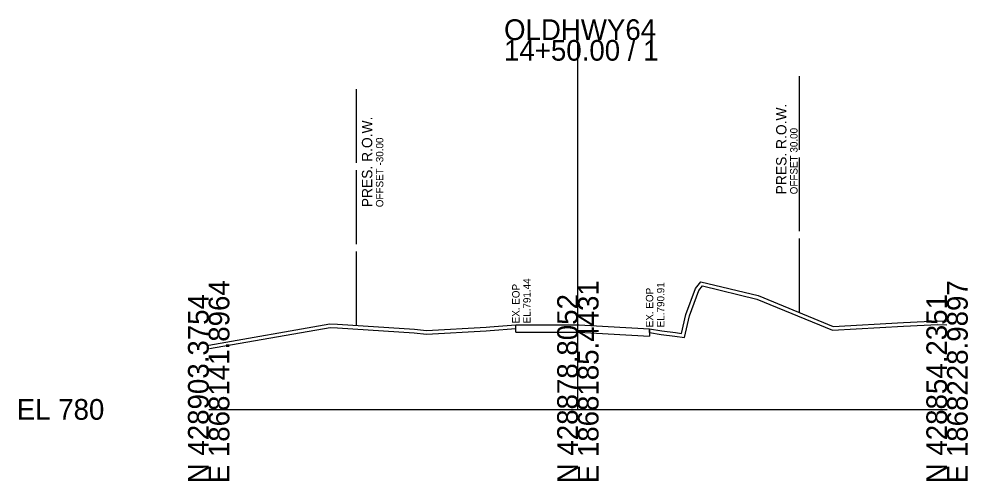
# Model space of a CAD drawing. Extents: x -452 to 3103, y -29 to 1600.
# Drawn here: x -25.7 to 102.8, y -17.7 to 44.8 of the extents above; entities that cross this region are included whole.
import ezdxf

# ---------------------------------------------------------------- set-up
doc = ezdxf.new("R2010")
doc.units = 0
for name, color, linetype in [('DESIGN - SHEET - Light Grid', 7, 'Continuous'), ('SURVEY - GROUND - Bottom of Topsoil Layer', 7, 'Continuous'), ('SURVEY - GROUND - Existing Pavement Layer', 7, 'Continuous'), ('SURVEY - GROUND - Existing Pavement Text', 7, 'Continuous'), ('SURVEY - GROUND - Top of Ground', 7, 'Continuous'), ('SURVEY - PROPERTY - ROW Lines', 7, 'Continuous'), ('SURVEY - PROPERTY - ROW Lines Text', 7, 'Continuous')]:
    doc.layers.add(name, color=color, linetype=linetype)

msp = doc.modelspace()

# ---------------------------------------------------------------- linework, layer by layer
at = {"layer": 'DESIGN - SHEET - Light Grid'}
for p, q in [((50, -8), (50, 42)), ((0, -8), (50, -8)), ((50, -8), (100, -8))]:
    msp.add_line(p, q, dxfattribs=at)
at = {"layer": 'SURVEY - GROUND - Bottom of Topsoil Layer'}
for p, q in [((41.6, 2.93), (41.6, 3.44)), ((59.71, 2.41), (59.71, 2.91))]:
    msp.add_line(p, q, dxfattribs=at)
for points in [[(59.71, 2.41), (61.3, 2.14), (63.14, 1.91), (64.43, 1.72), (65.12, 4.68), (66.4, 8.11), (66.87, 8.71), (74.26, 6.94), (84.49, 2.71), (94.11, 3.28), (98.74, 3.47), (99.98, 3.43)], [(0.09, 0.22), (16.45, 3.07), (17.43, 3.02), (27.85, 2.37), (29.5, 2.16), (37.6, 2.63), (38.12, 2.69), (41.6, 2.93)]]:
    msp.add_lwpolyline(points, dxfattribs=at)
at = {"layer": 'SURVEY - GROUND - Existing Pavement Layer'}
for p, q in [((41.6, 2.44), (41.6, 3.44)), ((59.71, 2.91), (59.71, 1.91)), ((41.6, 2.44), (45.14, 2.46)), ((45.14, 2.46), (49.07, 2.44)), ((49.07, 2.44), (50.18, 2.44)), ((50.18, 2.44), (54.09, 2.23)), ((54.09, 2.23), (59.71, 1.91))]:
    msp.add_line(p, q, dxfattribs=at)
at = {"layer": 'SURVEY - GROUND - Top of Ground'}
msp.add_lwpolyline([(0, 0.71), (16.42, 3.57), (17.46, 3.52), (27.89, 2.87), (29.51, 2.66), (37.56, 3.13), (38.07, 3.19), (41.6, 3.44), (45.14, 3.46), (49.07, 3.44), (50.18, 3.44), (54.09, 3.23), (59.71, 2.91), (61.37, 2.63), (63.2, 2.4), (64.05, 2.28), (64.64, 4.83), (65.95, 8.36), (66.67, 9.27), (74.42, 7.42), (84.57, 3.21), (94.08, 3.78), (98.74, 3.97), (100, 3.93)], dxfattribs=at)
at = {"layer": 'SURVEY - PROPERTY - ROW Lines'}
for p, q in [((80, 27.11), (80, 37.11)), ((20, 25.36), (20, 35.36)), ((80, 16.11), (80, 26.11)), ((20, 14.36), (20, 24.36)), ((80, 5.11), (80, 15.11)), ((20, 3.36), (20, 13.36))]:
    msp.add_line(p, q, dxfattribs=at)

# ---------------------------------------------------------------- texts
at = {"layer": 'DESIGN - SHEET - Light Grid'}
for s, p in [('OLDHWY64', (40, 42)), ('14+50.00 / 1', (40, 39.2)), ('EL 780', (-26, -9.4))]:
    msp.add_text(s, height=2.8, dxfattribs=at).set_placement(p)
for s, p in [('E 1868141.8964', (2.8, -18)), ('E 1868185.4431', (52.8, -18)), ('E 1868228.9897', (102.8, -18)), ('N 428903.3754', (0, -18)), ('N 428878.8052', (50, -18)), ('N 428854.2351', (100, -18))]:
    msp.add_text(s, height=2.8, rotation=90, dxfattribs=at).set_placement(p)
at = {"layer": 'SURVEY - GROUND - Existing Pavement Text'}
for s, p in [('EL.791.44', (43.6, 3.64)), ('EL.790.91', (61.71, 3.11)), ('EX. EOP', (42.1, 3.64)), ('EX. EOP', (60.21, 3.11))]:
    msp.add_text(s, height=1, rotation=90, dxfattribs=at).set_placement(p)
at = {"layer": 'SURVEY - PROPERTY - ROW Lines Text'}
for s, height, p in [('PRES. R.O.W.', 1.4, (78.25, 21.11)), ('PRES. R.O.W.', 1.4, (22.15, 19.36)), ('OFFSET 30.00', 1, (79.75, 21.11)), ('OFFSET -30.00', 1, (23.65, 19.36))]:
    msp.add_text(s, height=height, rotation=90, dxfattribs=at).set_placement(p)

doc.saveas('drawing.dxf')
